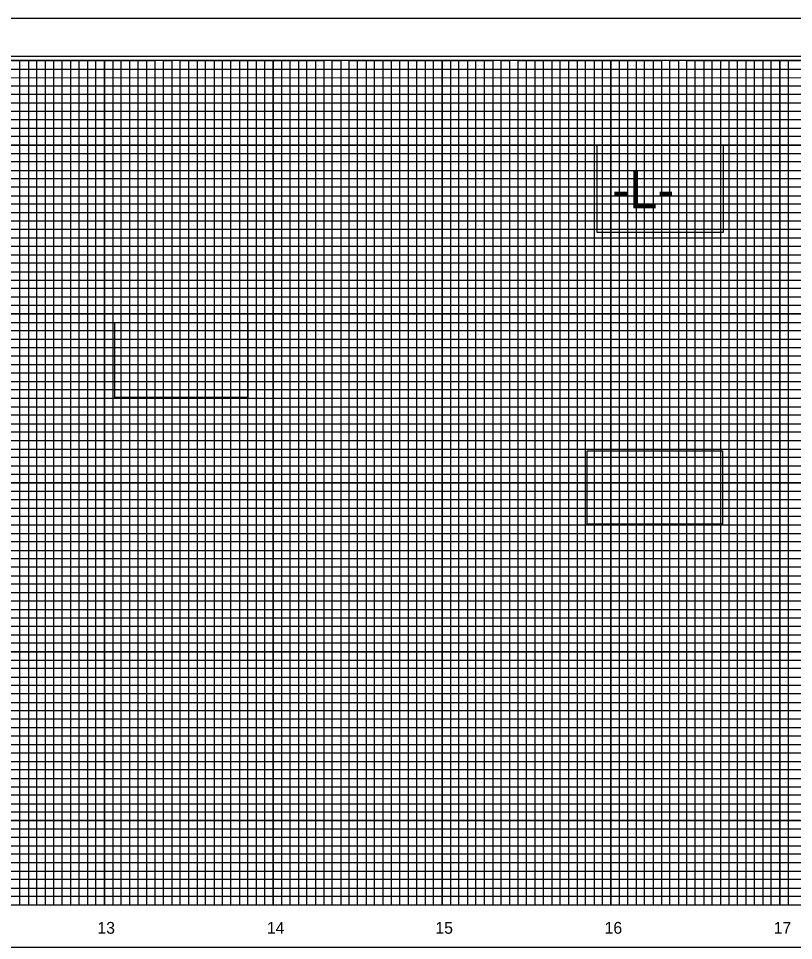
# Model space of a CAD drawing. Extents: x 557032 to 558716, y 513430 to 514605.
# Drawn here: x 557499 to 557958, y 513984 to 514530 of the extents above; entities that cross this region are included whole.
import ezdxf

# ---------------------------------------------------------------- set-up
doc = ezdxf.new("R2010")
doc.units = 0
for name, color, linetype in [('Exist Vertical Profile Horizontal Axis Label Major', 7, 'Continuous'), ('Prop Vertical Profile Curve Label', 7, 'Continuous'), ('Prop VPI Label', 7, 'Continuous'), ('Scratch_Level_5', 7, 'Continuous'), ('Sheet Cutting Line CELL', 7, 'Continuous'), ('Sheet DOT Grid CELL', 7, 'Continuous'), ('Sheet Layout Profile Border Port 1', 7, 'Continuous'), ('Sheet Plot Border Inside CELL', 7, 'Continuous'), ('Sheet Plot Border Outside CELL', 7, 'Continuous'), ('Sheet Profile CELL', 7, 'Continuous'), ('Sheet Profile Grid Major CELL', 7, 'Continuous'), ('Sheet Profile Grid Middle CELL', 7, 'Continuous'), ('Sheet Profile Grid Minor CELL', 7, 'Continuous')]:
    doc.layers.add(name, color=color, linetype=linetype)

msp = doc.modelspace()

# ---------------------------------------------------------------- linework, layer by layer
at = {"layer": 'Prop Vertical Profile Curve Label'}
for points in [[(557841.24, 514455.61), (557916.01, 514455.61), (557916.01, 514403.66), (557841.24, 514403.66)], [(557841.24, 514455.61), (557916.01, 514455.61), (557916.01, 514403.66), (557841.24, 514403.66)], [(557841.24, 514455.61), (557916.01, 514455.61), (557916.01, 514403.66), (557841.24, 514403.66)], [(557555.75, 514350.31), (557634.41, 514350.31), (557634.41, 514305.96), (557555.75, 514305.96)], [(557835.36, 514274.28), (557915.5, 514274.28), (557915.5, 514230.88), (557835.36, 514230.88)]]:
    msp.add_lwpolyline(points, close=True, dxfattribs=at)
at = {"layer": 'Prop VPI Label'}
msp.add_lwpolyline([(557841.24, 514455.61), (557916.01, 514455.61), (557916.01, 514403.66), (557841.24, 514403.66)], close=True, dxfattribs=at)
msp.add_lwpolyline([(557841.24, 514455.61), (557916.01, 514455.61), (557916.01, 514403.66), (557841.24, 514403.66)], close=True, dxfattribs=at)
at = {"layer": 'Scratch_Level_5'}
msp.add_lwpolyline([(557207.08, 514505.4), (557207.08, 513980.4), (558649.45, 513980.4), (558649.45, 514344.35), (558499.4, 514344.35), (558499.4, 514505.4)], close=True, dxfattribs=at)
at = {"layer": 'Sheet Cutting Line CELL'}
msp.add_line((558716.45, 514530.4), (557032.45, 514530.4), dxfattribs=at)
at = {"layer": 'Sheet DOT Grid CELL'}
for p, q in [((557499.45, 514005.4), (557499.45, 514505.4)), ((557549.45, 514005.4), (557549.45, 514505.4)), ((557599.45, 514005.4), (557599.45, 514505.4)), ((557649.45, 514005.4), (557649.45, 514505.4)), ((557699.45, 514005.4), (557699.45, 514505.4)), ((557749.45, 514005.4), (557749.45, 514505.4)), ((557799.45, 514005.4), (557799.45, 514505.4)), ((557849.45, 514005.4), (557849.45, 514505.4)), ((557899.45, 514005.4), (557899.45, 514505.4)), ((557949.45, 514005.4), (557949.45, 514505.4)), ((557499.45, 514011.34), (557499.45, 514488.82)), ((557549.45, 514011.3), (557549.45, 514488.82)), ((557599.45, 514011.26), (557599.45, 514488.82)), ((557649.45, 514011.23), (557649.45, 514488.82)), ((557699.45, 514011.19), (557699.45, 514488.82)), ((557749.45, 514011.15), (557749.45, 514488.82)), ((557799.45, 514011.12), (557799.45, 514488.82)), ((557849.45, 514011.08), (557849.45, 514488.82)), ((557899.45, 514011.04), (557899.45, 514488.82)), ((557949.45, 514011.01), (557949.45, 514488.82)), ((558499.4, 514455.4), (557199.45, 514455.4)), ((558484.51, 514455.4), (557203.74, 514455.4)), ((558499.4, 514405.4), (557199.45, 514405.4)), ((558484.51, 514405.4), (557203.83, 514405.4)), ((558499.45, 514355.4), (557199.45, 514355.4)), ((558484.51, 514355.4), (557203.92, 514355.4)), ((558699.45, 514305.4), (557199.45, 514305.4)), ((558693.5, 514305.4), (557204.01, 514305.4)), ((558699.45, 514255.4), (557199.45, 514255.4)), ((558693.5, 514255.4), (557204.1, 514255.4)), ((558699.45, 514205.4), (557199.45, 514205.4)), ((558693.5, 514205.4), (557204.18, 514205.4)), ((558699.45, 514155.4), (557199.45, 514155.4)), ((558693.5, 514155.4), (557204.27, 514155.4)), ((558699.45, 514105.4), (557199.45, 514105.4)), ((558693.5, 514105.4), (557204.36, 514105.4)), ((558699.45, 514055.4), (557199.45, 514055.4)), ((558693.5, 514055.4), (557204.45, 514055.4))]:
    msp.add_line(p, q, dxfattribs=at)
at = {"layer": 'Sheet Layout Profile Border Port 1'}
msp.add_lwpolyline([(557249.45, 514344.35), (557249.45, 514005.4), (558649.45, 514005.4), (558649.45, 514344.35)], dxfattribs=at)
at = {"layer": 'Sheet Plot Border Inside CELL'}
msp.add_lwpolyline([(557045.45, 513452.85), (558711.95, 513452.85), (558711.95, 514507.95), (557045.45, 514507.95)], close=True, dxfattribs=at)
at = {"layer": 'Sheet Plot Border Outside CELL'}
msp.add_lwpolyline([(557032.45, 513430.4), (558716.45, 513430.4), (558716.45, 514530.4), (557032.45, 514530.4)], close=True, dxfattribs=at)
at = {"layer": 'Sheet Profile CELL'}
msp.add_line((557199.45, 514005.4), (558699.45, 514005.4), dxfattribs=at)
msp.add_lwpolyline([(558699.45, 514505.4), (557199.45, 514505.4), (557199.45, 513455.4), (558699.45, 513455.4)], close=True, dxfattribs=at)
at = {"layer": 'Sheet Profile Grid Major CELL'}
for points in [[(557449.45, 514005.4), (557499.45, 514005.4), (557499.45, 514505.4), (557549.45, 514505.4), (557549.45, 514005.4), (557599.45, 514005.4), (557599.45, 514505.4), (557649.45, 514505.4), (557649.45, 514005.4), (557699.45, 514005.4), (557699.45, 514505.4), (557749.45, 514505.4), (557749.45, 514005.4), (557799.45, 514005.4), (557799.45, 514505.4), (557849.45, 514505.4), (557849.45, 514005.4), (557899.45, 514005.4), (557899.45, 514505.4), (557949.45, 514505.4), (557949.45, 514005.4), (557999.45, 514005.4)], [(557499.45, 514011.34), (557499.45, 514488.82)], [(557549.45, 514488.82), (557549.45, 514011.3)], [(557599.45, 514011.26), (557599.45, 514488.82)], [(557649.45, 514488.82), (557649.45, 514011.23)], [(557699.45, 514011.19), (557699.45, 514488.82)], [(557749.45, 514488.82), (557749.45, 514011.15)], [(557799.45, 514011.12), (557799.45, 514488.82)], [(557849.45, 514488.82), (557849.45, 514011.08)], [(557899.45, 514011.04), (557899.45, 514488.82)], [(557949.45, 514488.82), (557949.45, 514011.01)], [(557199.45, 514455.4), (558499.45, 514455.4)], [(557203.74, 514455.4), (558484.51, 514455.4)], [(558499.45, 514405.4), (557199.45, 514405.4), (557199.45, 514355.4), (558499.45, 514355.4)], [(558484.51, 514405.4), (557203.83, 514405.4)], [(557203.92, 514355.4), (558484.51, 514355.4)], [(558699.45, 514305.4), (557199.45, 514305.4), (557199.45, 514255.4), (558699.45, 514255.4)], [(558693.5, 514305.4), (557204.01, 514305.4)], [(557204.1, 514255.4), (558693.5, 514255.4)], [(558699.45, 514205.4), (557199.45, 514205.4), (557199.45, 514155.4), (558699.45, 514155.4)], [(558693.5, 514205.4), (557204.18, 514205.4)], [(557204.27, 514155.4), (558693.5, 514155.4)], [(558699.45, 514105.4), (557199.45, 514105.4), (557199.45, 514105.4), (557199.45, 514055.4), (558699.45, 514055.4)], [(558693.5, 514105.4), (557204.36, 514105.4)], [(557204.45, 514055.4), (558693.5, 514055.4)]]:
    msp.add_lwpolyline(points, dxfattribs=at)
at = {"layer": 'Sheet Profile Grid Middle CELL'}
for p, q in [((557199.45, 514480.4), (558499.4, 514480.4)), ((557203.7, 514480.4), (558484.51, 514480.4))]:
    msp.add_line(p, q, dxfattribs=at)
for points in [[(557474.45, 514005.4), (557524.45, 514005.4), (557524.45, 514505.4), (557574.45, 514505.4), (557574.45, 514005.4), (557624.45, 514005.4), (557624.45, 514505.4), (557674.45, 514505.4), (557674.45, 514005.4), (557724.45, 514005.4), (557724.45, 514505.4), (557774.45, 514505.4), (557774.45, 514005.4), (557824.45, 514005.4), (557824.45, 514005.4), (557824.45, 514505.4), (557874.45, 514505.4), (557874.45, 514005.4), (557924.45, 514005.4), (557924.45, 514505.4), (557974.45, 514505.4)], [(557524.45, 514011.32), (557524.45, 514488.82)], [(557574.45, 514488.82), (557574.45, 514011.28)], [(557624.45, 514011.25), (557624.45, 514488.82)], [(557674.45, 514488.82), (557674.45, 514011.21)], [(557724.45, 514011.17), (557724.45, 514488.82)], [(557774.45, 514488.82), (557774.45, 514011.14)], [(557824.45, 514011.1), (557824.45, 514488.82)], [(557874.45, 514488.82), (557874.45, 514011.06)], [(557924.45, 514011.03), (557924.45, 514488.82)], [(558499.45, 514430.4), (557199.45, 514430.4), (557199.45, 514380.4), (558499.45, 514380.4)], [(558484.51, 514430.4), (557203.79, 514430.4)], [(557203.88, 514380.4), (558484.51, 514380.4)], [(558699.45, 514330.4), (557199.45, 514330.4), (557199.45, 514280.4), (558524.45, 514280.4)], [(558484.51, 514330.4), (557203.96, 514330.4)], [(557204.05, 514280.4), (558524.45, 514280.4)], [(558699.45, 514230.4), (557199.45, 514230.4), (557199.45, 514180.4), (558699.45, 514180.4)], [(558693.5, 514230.4), (557204.14, 514230.4)], [(557204.23, 514180.4), (558693.5, 514180.4)], [(558699.45, 514130.4), (557199.45, 514130.4), (557199.45, 514080.4), (558699.45, 514080.4)], [(558693.5, 514130.4), (557204.32, 514130.4)], [(557204.4, 514080.4), (558693.5, 514080.4)], [(558699.45, 514030.4), (557199.45, 514030.4)], [(558444.08, 514030.4), (557204.49, 514030.4)]]:
    msp.add_lwpolyline(points, dxfattribs=at)
at = {"layer": 'Sheet Profile Grid Minor CELL'}
for p, q in [((557249.45, 514500.4), (558499.45, 514500.4)), ((558499.45, 514495.4), (557249.45, 514495.05)), ((557249.45, 514490.4), (558499.45, 514490.4)), ((558499.4, 514370.4), (557249.45, 514370.4)), ((558484.51, 514370.4), (557249.45, 514370.4)), ((558499.45, 514365.4), (557249.45, 514365.4)), ((558484.51, 514365.4), (557249.45, 514365.4)), ((558499.45, 514360.4), (557249.45, 514360.4)), ((558484.51, 514360.4), (557249.45, 514360.4)), ((557249.45, 514350.4), (558499.45, 514350.4)), ((557249.45, 514350.4), (558484.51, 514350.4)), ((558499.45, 514345.4), (557249.45, 514345.4)), ((558484.51, 514345.4), (557249.45, 514345.4)), ((557249.45, 514340.4), (558649.45, 514340.4)), ((557249.45, 514340.4), (558484.51, 514340.4)), ((558649.45, 514320.4), (557249.45, 514320.4)), ((558484.51, 514320.4), (557249.45, 514320.4)), ((557249.45, 514315.4), (558649.45, 514315.4)), ((557249.45, 514315.4), (558649.45, 514315.4)), ((558649.45, 514295.4), (557249.45, 514295.4)), ((558649.45, 514295.4), (557249.45, 514295.4)), ((557249.45, 514290.4), (558649.45, 514290.4)), ((557249.45, 514290.4), (558649.45, 514290.4)), ((558649.45, 514270.4), (557249.45, 514270.4)), ((558649.45, 514270.4), (557249.45, 514270.4)), ((557249.45, 514265.4), (558649.45, 514265.4)), ((557249.45, 514265.4), (558649.45, 514265.4)), ((558649.45, 514260.4), (557249.45, 514260.4)), ((558649.45, 514260.4), (557249.45, 514260.4)), ((557249.45, 514250.4), (558649.45, 514250.4)), ((557249.45, 514250.4), (558649.45, 514250.4)), ((558649.45, 514245.4), (557249.45, 514245.4)), ((558649.45, 514245.4), (557249.45, 514245.4)), ((557249.45, 514240.4), (558649.45, 514240.4)), ((557249.45, 514240.4), (558649.45, 514240.4)), ((558649.45, 514235.4), (557249.45, 514235.4)), ((558649.45, 514235.4), (557249.45, 514235.4)), ((557249.45, 514225.4), (558649.45, 514225.4)), ((557249.45, 514225.4), (558649.45, 514225.4)), ((558649.45, 514220.4), (557249.45, 514220.4)), ((558649.45, 514220.4), (557249.45, 514220.4)), ((557249.45, 514215.4), (558649.45, 514215.4)), ((557249.45, 514215.4), (558649.45, 514215.4)), ((558649.45, 514210.4), (557249.45, 514210.4)), ((558649.45, 514210.4), (557249.45, 514210.4)), ((557249.45, 514200.4), (558649.45, 514200.4)), ((557249.45, 514200.4), (558649.45, 514200.4)), ((558649.45, 514195.4), (557249.45, 514195.4)), ((558649.45, 514195.4), (557249.45, 514195.4)), ((557249.45, 514190.4), (558649.45, 514190.4)), ((557249.45, 514190.4), (558649.45, 514190.4)), ((558649.45, 514185.4), (557249.45, 514185.4)), ((558649.45, 514185.4), (557249.45, 514185.4)), ((557249.45, 514175.4), (558649.45, 514175.4)), ((557249.45, 514175.4), (558649.45, 514175.4)), ((558649.45, 514170.4), (557249.45, 514170.4)), ((558649.45, 514170.4), (557249.45, 514170.4)), ((557249.45, 514165.4), (558649.45, 514165.4)), ((557249.45, 514165.4), (558649.45, 514165.4)), ((558649.45, 514160.4), (557249.45, 514160.4)), ((558649.45, 514160.4), (557249.45, 514160.4)), ((557249.45, 514150.4), (558649.45, 514150.4)), ((557249.45, 514150.4), (558649.45, 514150.4)), ((558649.45, 514145.4), (557249.45, 514145.4)), ((558649.45, 514145.4), (557249.45, 514145.4)), ((557249.45, 514140.4), (558649.45, 514140.4)), ((557249.45, 514140.4), (558649.45, 514140.4)), ((558649.45, 514135.4), (557249.45, 514135.4)), ((558649.45, 514135.4), (557249.45, 514135.4)), ((557249.45, 514125.4), (558649.45, 514125.4)), ((557249.45, 514125.4), (558649.45, 514125.4)), ((558649.45, 514120.4), (557249.45, 514120.4)), ((558649.45, 514120.4), (557249.45, 514120.4)), ((558649.45, 514115.4), (557249.45, 514115.4)), ((558649.45, 514115.4), (557249.45, 514115.4)), ((558649.45, 514110.4), (557249.45, 514110.4)), ((558649.45, 514110.4), (557249.45, 514110.4)), ((557249.45, 514100.4), (558649.45, 514100.4)), ((557249.45, 514100.4), (558649.45, 514100.4)), ((558649.45, 514095.4), (557249.45, 514095.4)), ((558649.45, 514095.4), (557249.45, 514095.4)), ((557249.45, 514090.4), (558649.45, 514090.4)), ((557249.45, 514090.4), (558649.45, 514090.4)), ((558649.45, 514085.4), (557249.45, 514085.4)), ((558649.45, 514085.4), (557249.45, 514085.4)), ((557249.45, 514075.4), (558649.45, 514075.4)), ((557249.45, 514075.4), (558649.45, 514075.4)), ((558649.45, 514070.4), (557249.45, 514070.4)), ((558649.45, 514070.4), (557249.45, 514070.4)), ((557249.45, 514065.4), (558649.45, 514065.4)), ((557249.45, 514065.4), (558649.45, 514065.4)), ((558649.45, 514060.4), (557249.45, 514060.4)), ((558649.45, 514060.4), (557249.45, 514060.4)), ((557249.45, 514050.4), (558649.45, 514050.4)), ((557249.45, 514050.4), (558649.45, 514050.4)), ((558649.45, 514045.4), (557249.45, 514045.4)), ((558649.45, 514045.4), (557249.45, 514045.4)), ((557249.45, 514040.4), (558649.45, 514040.4)), ((557249.45, 514040.4), (558649.45, 514040.4)), ((558649.45, 514035.4), (557249.45, 514035.4)), ((558447.22, 514035.4), (557249.45, 514035.4)), ((557249.45, 514025.4), (558649.45, 514025.4)), ((557249.45, 514025.4), (558440.95, 514025.4)), ((558649.45, 514020.4), (557249.45, 514020.4)), ((558437.82, 514020.4), (557249.45, 514020.4)), ((557249.45, 514015.4), (558649.45, 514015.4)), ((557249.45, 514015.4), (558434.68, 514015.4))]:
    msp.add_line(p, q, dxfattribs=at)
for points in [[(557494.45, 514505.4), (557504.45, 514505.4), (557504.45, 514005.4), (557509.45, 514005.4), (557509.45, 514505.4), (557514.45, 514505.4), (557514.45, 514005.4), (557519.45, 514005.4), (557519.45, 514505.4), (557529.45, 514505.4), (557529.45, 514005.4), (557534.45, 514005.4), (557534.45, 514505.4), (557539.45, 514505.4), (557539.45, 514005.4), (557544.45, 514005.4), (557544.45, 514505.4), (557554.45, 514505.4), (557554.45, 514005.4), (557559.45, 514005.4), (557559.45, 514505.4), (557564.45, 514505.4), (557564.45, 514005.4), (557569.45, 514005.4), (557569.45, 514505.4), (557579.45, 514505.4), (557579.45, 514005.4), (557584.45, 514005.4), (557584.45, 514505.4), (557589.45, 514505.4), (557589.45, 514005.4), (557594.45, 514005.4), (557594.45, 514505.4), (557604.45, 514505.4), (557604.45, 514005.4), (557609.45, 514005.4), (557609.45, 514505.4), (557614.45, 514505.4), (557614.45, 514005.4), (557619.45, 514005.4), (557619.45, 514505.4), (557629.45, 514505.4), (557629.45, 514005.4), (557634.45, 514005.4), (557634.45, 514505.4), (557639.45, 514505.4), (557639.45, 514005.4), (557644.45, 514005.4), (557644.45, 514505.4), (557654.45, 514505.4), (557654.45, 514005.4), (557659.45, 514005.4), (557659.45, 514505.4), (557664.45, 514505.4), (557664.45, 514005.4), (557669.45, 514005.4), (557669.45, 514505.4), (557679.45, 514505.4), (557679.45, 514005.4), (557684.45, 514005.4), (557684.45, 514505.4), (557689.45, 514505.4), (557689.45, 514005.4), (557694.45, 514005.4), (557694.45, 514505.4), (557704.45, 514505.4), (557704.45, 514005.4), (557709.45, 514005.4), (557709.45, 514505.4), (557714.45, 514505.4), (557714.45, 514005.4), (557719.45, 514005.4), (557719.45, 514505.4), (557729.45, 514505.4), (557729.45, 514005.4), (557734.45, 514005.4), (557734.45, 514505.4), (557739.45, 514505.4), (557739.45, 514005.4), (557744.45, 514005.4), (557744.45, 514505.4), (557754.45, 514505.4), (557754.45, 514005.4), (557759.45, 514005.4), (557759.45, 514505.4), (557764.45, 514505.4), (557764.45, 514005.4), (557769.45, 514005.4), (557769.45, 514505.4), (557779.45, 514505.4)], [(557779.45, 514505.4), (557779.45, 514005.4), (557784.45, 514005.4), (557784.45, 514505.4), (557789.45, 514505.4), (557789.45, 514005.4), (557794.45, 514005.4), (557794.45, 514505.4), (557804.45, 514505.4), (557804.45, 514005.4), (557809.45, 514005.4), (557809.45, 514505.4), (557814.45, 514505.4), (557814.45, 514005.4), (557819.45, 514005.4), (557819.45, 514505.4), (557829.45, 514505.4), (557829.45, 514005.4), (557834.45, 514005.4), (557834.45, 514505.4), (557839.45, 514505.4), (557839.45, 514005.4), (557844.45, 514005.4), (557844.45, 514505.4), (557854.45, 514505.4), (557854.45, 514005.4), (557859.45, 514005.4), (557859.45, 514505.4), (557864.45, 514505.4), (557864.45, 514005.4), (557869.45, 514005.4), (557869.45, 514505.4), (557879.45, 514505.4), (557879.45, 514005.4), (557884.45, 514005.4), (557884.45, 514505.4), (557889.45, 514505.4), (557889.45, 514005.4), (557894.45, 514005.4), (557894.45, 514505.4), (557904.45, 514505.4), (557904.45, 514005.4), (557904.45, 514005.4), (557909.45, 514005.4), (557909.45, 514505.4), (557914.45, 514505.4), (557914.45, 514005.4), (557919.45, 514005.4), (557919.45, 514505.4), (557929.45, 514505.4), (557929.45, 514005.4), (557934.45, 514005.4), (557934.45, 514505.4), (557939.45, 514505.4), (557939.45, 514005.4), (557944.45, 514005.4), (557944.45, 514505.4), (557954.45, 514505.4), (557954.45, 514005.4), (557959.45, 514005.4)], [(558499.45, 514485.4), (557249.45, 514485.4), (557249.45, 514475.4), (558499.45, 514475.4)], [(558484.51, 514485.4), (557249.45, 514485.4), (557249.45, 514475.4), (558484.51, 514475.4)], [(557504.45, 514488.82), (557504.45, 514011.33)], [(557509.45, 514011.33), (557509.45, 514488.82)], [(557514.45, 514488.82), (557514.45, 514011.33)], [(557519.45, 514011.32), (557519.45, 514488.82)], [(557529.45, 514488.82), (557529.45, 514011.32)], [(557534.45, 514011.31), (557534.45, 514488.82)], [(557539.45, 514488.82), (557539.45, 514011.31)], [(557544.45, 514011.3), (557544.45, 514488.82)], [(557554.45, 514488.82), (557554.45, 514011.3)], [(557559.45, 514011.29), (557559.45, 514488.82)], [(557564.45, 514488.82), (557564.45, 514011.29)], [(557569.45, 514011.29), (557569.45, 514488.82)], [(557579.45, 514488.82), (557579.45, 514011.28)], [(557584.45, 514011.28), (557584.45, 514488.82)], [(557589.45, 514488.82), (557589.45, 514011.27)], [(557594.45, 514011.27), (557594.45, 514488.82)], [(557604.45, 514488.82), (557604.45, 514011.26)], [(557609.45, 514011.26), (557609.45, 514488.82)], [(557614.45, 514488.82), (557614.45, 514011.25)], [(557619.45, 514011.25), (557619.45, 514488.82)], [(557629.45, 514488.82), (557629.45, 514011.24)], [(557634.45, 514011.24), (557634.45, 514488.82)], [(557639.45, 514488.82), (557639.45, 514011.24)], [(557644.45, 514011.23), (557644.45, 514488.82)], [(557654.45, 514488.82), (557654.45, 514011.22)], [(557659.45, 514011.22), (557659.45, 514488.82)], [(557664.45, 514488.82), (557664.45, 514011.22)], [(557669.45, 514011.21), (557669.45, 514488.82)], [(557679.45, 514488.82), (557679.45, 514011.21)], [(557684.45, 514011.2), (557684.45, 514488.82)], [(557689.45, 514488.82), (557689.45, 514011.2)], [(557694.45, 514011.19), (557694.45, 514488.82)], [(557704.45, 514488.82), (557704.45, 514011.19)], [(557709.45, 514011.18), (557709.45, 514488.82)], [(557714.45, 514488.82), (557714.45, 514011.18)], [(557719.45, 514011.18), (557719.45, 514488.82)], [(557729.45, 514488.82), (557729.45, 514011.17)], [(557734.45, 514011.17), (557734.45, 514488.82)], [(557739.45, 514488.82), (557739.45, 514011.16)], [(557744.45, 514011.16), (557744.45, 514488.82)], [(557754.45, 514488.82), (557754.45, 514011.15)], [(557759.45, 514011.15), (557759.45, 514488.82)], [(557764.45, 514488.82), (557764.45, 514011.14)], [(557769.45, 514011.14), (557769.45, 514488.82)], [(557779.45, 514488.82), (557779.45, 514011.13)], [(557784.45, 514011.13), (557784.45, 514488.82)], [(557789.45, 514488.82), (557789.45, 514011.13)], [(557794.45, 514011.12), (557794.45, 514488.82)], [(557804.45, 514488.82), (557804.45, 514011.11)], [(557809.45, 514011.11), (557809.45, 514488.82)], [(557814.45, 514488.82), (557814.45, 514011.11)], [(557819.45, 514011.1), (557819.45, 514488.82)], [(557829.45, 514488.82), (557829.45, 514011.1)], [(557834.45, 514011.09), (557834.45, 514488.82)], [(557839.45, 514488.82), (557839.45, 514011.09)], [(557844.45, 514011.08), (557844.45, 514488.82)], [(557854.45, 514488.82), (557854.45, 514011.08)], [(557859.45, 514011.07), (557859.45, 514488.82)], [(557864.45, 514488.82), (557864.45, 514011.07)], [(557869.45, 514011.07), (557869.45, 514488.82)], [(557879.45, 514488.82), (557879.45, 514011.06)], [(557884.45, 514011.06), (557884.45, 514488.82)], [(557889.45, 514488.82), (557889.45, 514011.05)], [(557894.45, 514011.05), (557894.45, 514488.82)], [(557904.45, 514488.82), (557904.45, 514011.04)], [(557909.45, 514011.04), (557909.45, 514488.82)], [(557914.45, 514488.82), (557914.45, 514011.03)], [(557919.45, 514011.03), (557919.45, 514488.82)], [(557929.45, 514488.82), (557929.45, 514011.02)], [(557934.45, 514011.02), (557934.45, 514488.82)], [(557939.45, 514488.82), (557939.45, 514011.02)], [(557944.45, 514011.01), (557944.45, 514488.82)], [(557954.45, 514488.82), (557954.45, 514011)], [(558499.4, 514470.4), (557249.45, 514470.4), (557249.45, 514465.4), (558499.45, 514465.4)], [(558484.51, 514470.4), (557249.45, 514470.4), (557249.45, 514465.4), (558484.51, 514465.4)], [(558499.45, 514460.4), (557249.45, 514460.4), (557249.45, 514450.4), (558499.45, 514450.4)], [(558484.51, 514460.4), (557249.45, 514460.4), (557249.45, 514450.4), (558484.51, 514450.4)], [(558499.45, 514445.4), (557249.45, 514445.4), (557249.45, 514440.4), (558499.45, 514440.4)], [(558484.51, 514445.4), (557249.45, 514445.4), (557249.45, 514440.4), (558484.51, 514440.4)], [(558499.45, 514435.4), (557249.45, 514435.4), (557249.45, 514425.4), (558499.45, 514425.4)], [(558484.51, 514435.4), (557249.45, 514435.4), (557249.45, 514425.4), (558484.51, 514425.4)], [(558499.45, 514420.4), (557249.45, 514420.4), (557249.45, 514415.4), (558499.45, 514415.4)], [(558484.51, 514420.4), (557249.45, 514420.4), (557249.45, 514415.4), (558484.51, 514415.4)], [(558499.45, 514410.4), (557249.45, 514410.4), (557249.45, 514400.4), (558499.45, 514400.4)], [(558484.51, 514410.4), (557249.45, 514410.4), (557249.45, 514400.4), (558484.51, 514400.4)], [(558499.45, 514395.3), (557249.55, 514395.3), (557249.55, 514390.4), (558499.45, 514390.4)], [(558484.51, 514395.3), (557249.55, 514395.3), (557249.55, 514390.4), (558484.51, 514390.4)], [(558499.45, 514385.4), (557249.45, 514385.4), (557249.45, 514375.4), (558499.45, 514375.4)], [(558484.51, 514385.4), (557249.45, 514385.4), (557249.45, 514375.4), (558484.51, 514375.4)], [(558649.45, 514335.4), (557249.45, 514335.4), (557249.45, 514325.4), (558649.45, 514325.4)], [(558484.51, 514335.4), (557249.45, 514335.4), (557249.45, 514325.4), (558484.51, 514325.4)], [(558649.45, 514310.4), (557249.45, 514310.4), (557249.45, 514300.4), (558649.45, 514300.4)], [(558649.45, 514310.4), (557249.45, 514310.4), (557249.45, 514300.4), (558649.45, 514300.4)], [(558649.45, 514285.4), (557249.45, 514285.4), (557249.45, 514275.4), (558649.45, 514275.4)], [(558649.45, 514285.4), (557249.45, 514285.4), (557249.45, 514275.4), (558649.45, 514275.4)], [(558649.45, 514010.4), (557249.45, 514010.4)]]:
    msp.add_lwpolyline(points, dxfattribs=at)

# ---------------------------------------------------------------- texts
at = {"layer": 'Exist Vertical Profile Horizontal Axis Label Major'}
for s, p in [('13', (557545.35, 513988.37)), ('14', (557645.71, 513988.37)), ('15', (557745.51, 513988.37)), ('16', (557845.71, 513988.37)), ('17', (557945.87, 513988.37))]:
    msp.add_text(s, height=7, dxfattribs=at).set_placement(p)
at = {"layer": 'Prop Vertical Profile Curve Label'}
msp.add_text('-L-', height=22.5, dxfattribs=at).set_placement((557850.23, 514417.9))

doc.saveas('drawing.dxf')
